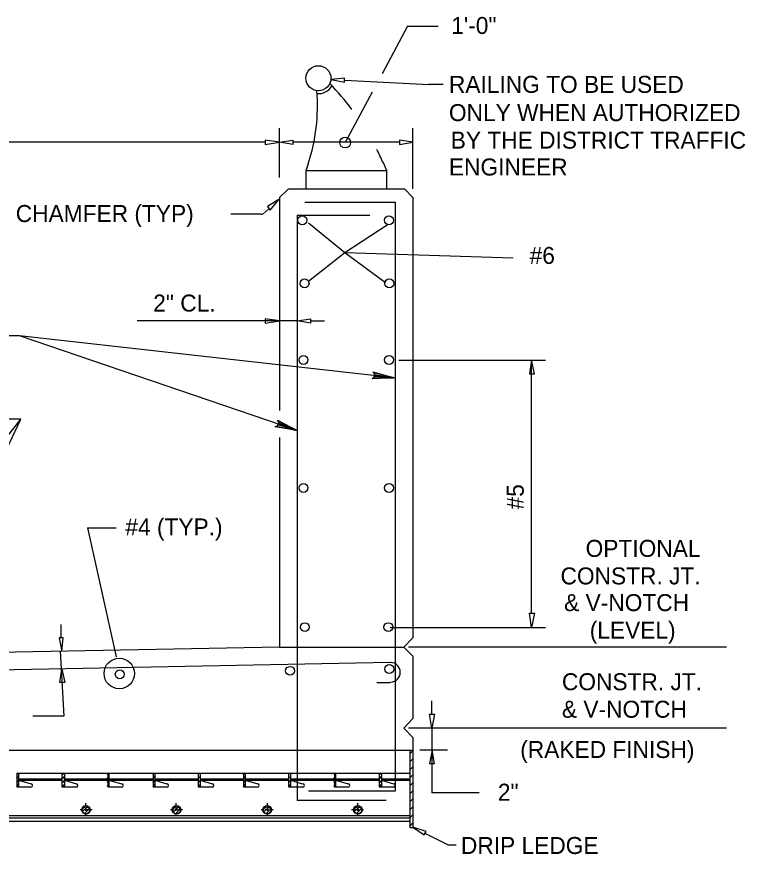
# Model space of a CAD drawing. Extents: x -24512 to -22484, y 4569 to 6351.
# Drawn here: x -23764.3 to -23635.6, y 6048 to 6195.9 of the extents above; entities that cross this region are included whole.
import ezdxf

# ---------------------------------------------------------------- set-up
doc = ezdxf.new("R2010")
doc.units = 0
for name, color, linetype in [('10', 7, 'Continuous'), ('4', 7, 'Continuous'), ('5', 7, 'Continuous'), ('8', 7, 'Continuous'), ('9', 7, 'Continuous')]:
    doc.layers.add(name, color=color, linetype=linetype)

# ---------------------------------------------------------------- blocks, each defined once
blk = doc.blocks.new('JUQ000')
at = {"layer": '4'}
for p, q in [((71.0975, 21.771125), (71.421875, 22.095625)), ((71.237875, 21.6265), (71.566625, 21.95525))]:
    blk.add_line(p, q, dxfattribs=at)
blk = doc.blocks.new('_X')
at = {"layer": '4'}
for p, q in [((63.193375, 24.416625), (63.299125, 24.522375)), ((63.193375, 24.1315), (63.3445, 24.282625)), ((63.193375, 23.846375), (63.3445, 23.9975)), ((63.193375, 23.56125), (63.3445, 23.712375))]:
    blk.add_line(p, q, dxfattribs=at)
blk = doc.blocks.new('JUQ007')
at = {"layer": '4'}
for p, q in [((153.103125, 337.29275), (153.30475, 337.494375)), ((153.103125, 336.7225), (153.30475, 336.924125)), ((153.103125, 336.15225), (153.30475, 336.353875)), ((153.103125, 335.582), (153.30475, 335.783625)), ((153.103125, 335.01175), (153.30475, 335.213375)), ((153.103125, 334.4415), (153.30475, 334.643125)), ((153.103125, 333.87125), (153.30475, 334.072875)), ((153.103125, 333.301), (153.30475, 333.502625)), ((153.103125, 332.73075), (153.30475, 332.932375)), ((153.103125, 332.1605), (153.30475, 332.362125))]:
    blk.add_line(p, q, dxfattribs=at)

msp = doc.modelspace()

# ---------------------------------------------------------------- linework, layer by layer
at = {"layer": '10'}
for p, q in [((-23695.25, 6194.21), (-23699.75, 6185.84)), ((-23695.25, 6194.21), (-23689.87, 6194.21)), ((-23706.41, 6184.7), (-23691.45, 6183.95)), ((-23688.96, 6183.95), (-23691.45, 6183.95)), ((-23701.5, 6182.59), (-23706.28, 6173.69)), ((-23717.89, 6167.5), (-23717.89, 6176.22)), ((-23694.32, 6165.5), (-23694.32, 6176.22)), ((-23720.38, 6173.73), (-23842.45, 6173.73)), ((-23696.69, 6173.73), (-23715.52, 6173.73)), ((-23719.76, 6162.01), (-23720.5, 6161.26)), ((-23721.13, 6161.01), (-23726.49, 6161.01)), ((-23706.33, 6154.19), (-23712.75, 6159.46)), ((-23698.69, 6159.22), (-23706.33, 6154.19)), ((-23706.33, 6154.19), (-23712.75, 6149.17)), ((-23699.18, 6148.93), (-23706.33, 6154.19)), ((-23676.64, 6153.27), (-23706.33, 6154.19)), ((-23714.77, 6142.18), (-23742.99, 6142.18)), ((-23712.4, 6142.18), (-23709.91, 6142.18)), ((-23763.77, 6139.57), (-23778.53, 6139.57)), ((-23697.61, 6132.14), (-23763.77, 6139.57)), ((-23714.77, 6122.84), (-23763.77, 6139.57)), ((-23696.81, 6135.24), (-23670.88, 6135.24)), ((-23673.37, 6090.56), (-23673.37, 6135.24)), ((-23797.56, 6081.71), (-23763.52, 6124.85)), ((-23783.85, 6082.33), (-23763.52, 6124.85)), ((-23763.52, 6124.85), (-23778.92, 6124.85)), ((-23751.76, 6105.63), (-23746.74, 6105.63)), ((-23751.76, 6105.63), (-23746.74, 6082.84)), ((-23756.41, 6086.2), (-23756.41, 6088.57)), ((-23698.31, 6088.07), (-23670.88, 6088.07)), ((-23756.58, 6083.84), (-23755.98, 6072.38)), ((-23638.96, 6084.58), (-23695.07, 6084.58)), ((-23690.95, 6072.73), (-23690.95, 6075.1)), ((-23755.98, 6072.38), (-23761.4, 6072.38)), ((-23638.96, 6070.24), (-23695.07, 6070.24)), ((-23690.95, 6070.24), (-23690.95, 6058.86)), ((-23688.21, 6066.37), (-23693.07, 6066.37)), ((-23682.62, 6058.86), (-23690.95, 6058.86)), ((-23752.05, 6056.4), (-23752.05, 6057.02)), ((-23736.09, 6056.4), (-23736.09, 6057.02)), ((-23720.01, 6056.4), (-23720.01, 6057.02)), ((-23704.05, 6056.4), (-23704.05, 6057.02)), ((-23753.05, 6055.9), (-23752.67, 6055.9)), ((-23752.3, 6055.9), (-23751.8, 6055.9)), ((-23752.05, 6055.65), (-23752.05, 6056.15)), ((-23752.05, 6054.78), (-23752.05, 6055.28)), ((-23751.55, 6055.9), (-23750.93, 6055.9)), ((-23737.09, 6055.9), (-23736.59, 6055.9)), ((-23736.34, 6055.9), (-23735.72, 6055.9)), ((-23736.09, 6055.65), (-23736.09, 6056.15)), ((-23736.09, 6054.78), (-23736.09, 6055.28)), ((-23735.47, 6055.9), (-23734.97, 6055.9)), ((-23721.13, 6055.9), (-23720.63, 6055.9)), ((-23720.38, 6055.9), (-23719.76, 6055.9)), ((-23720.01, 6055.65), (-23720.01, 6056.15)), ((-23720.01, 6054.78), (-23720.01, 6055.28)), ((-23719.51, 6055.9), (-23719.01, 6055.9)), ((-23705.17, 6055.9), (-23704.54, 6055.9)), ((-23704.29, 6055.9), (-23703.8, 6055.9)), ((-23704.05, 6055.65), (-23704.05, 6056.15)), ((-23704.05, 6054.78), (-23704.05, 6055.28)), ((-23703.42, 6055.9), (-23703.05, 6055.9)), ((-23692.08, 6051.66), (-23688.08, 6049.67)), ((-23688.08, 6049.67), (-23686.71, 6049.67))]:
    msp.add_line(p, q, dxfattribs=at)
for points in [[(-23706.41, 6184.33), (-23706.41, 6185.08), (-23708.78, 6184.83)], [(-23720.38, 6174.1), (-23720.38, 6173.36), (-23717.89, 6173.73)], [(-23715.52, 6174.1), (-23715.52, 6173.36), (-23717.89, 6173.73)], [(-23696.69, 6174.1), (-23696.69, 6173.36), (-23694.32, 6173.73)], [(-23720.01, 6162.38), (-23719.51, 6161.76), (-23718.01, 6163.63)], [(-23720.38, 6142.56), (-23720.38, 6141.81), (-23717.89, 6142.18)], [(-23712.4, 6142.56), (-23712.4, 6141.81), (-23714.77, 6142.18)], [(-23673.75, 6132.87), (-23672.87, 6132.87), (-23673.37, 6135.24)], [(-23673.75, 6090.56), (-23672.87, 6090.56), (-23673.37, 6088.07)], [(-23756.04, 6086.2), (-23756.79, 6086.2), (-23756.29, 6083.83)], [(-23755.79, 6078.34), (-23756.66, 6078.34), (-23756.29, 6080.71)], [(-23691.4, 6072.73), (-23690.5, 6072.73), (-23690.95, 6070.24)], [(-23691.39, 6064.01), (-23690.49, 6064.01), (-23690.94, 6066.37)], [(-23692.32, 6051.41), (-23691.95, 6052.04), (-23694.32, 6052.78)]]:
    msp.add_lwpolyline(points, close=True, dxfattribs=at)
for points in [[(-23701.22, 6133.01), (-23701.12, 6132.73), (-23697.61, 6132.14), (-23701.22, 6133.01), (-23701.39, 6133.19), (-23697.61, 6132.14), (-23701.16, 6132.36), (-23701.31, 6132.11), (-23697.61, 6132.14), (-23701.53, 6131.96), (-23701.31, 6132.11)], [(-23718.11, 6124.47), (-23718.07, 6124.17), (-23714.77, 6122.84), (-23718.11, 6124.47), (-23718.24, 6124.68), (-23714.77, 6122.84), (-23718.18, 6123.82), (-23718.39, 6123.61), (-23714.77, 6122.84), (-23718.64, 6123.51), (-23718.39, 6123.61)]]:
    msp.add_lwpolyline(points, dxfattribs=at)
for centre, radius in [((-23706.28, 6173.69), 0.963), ((-23746.16, 6079.92), 2.69)]:
    msp.add_circle(centre, radius, dxfattribs=at)
for centre, start, end in [((-23691.51, 6184.77), 267.3542, 270), ((-23721.13, 6161.81), 270, 313.1659)]:
    msp.add_arc(centre, 0.788, start, end, dxfattribs=at)
at = {"layer": '5'}
for p, q in [((-23756.29, 6062.26), (-23763.9, 6062.26)), ((-23756.29, 6061.26), (-23763.9, 6061.26)), ((-23756.29, 6061.01), (-23763.9, 6061.01)), ((-23761.65, 6060.39), (-23763.9, 6061.01)), ((-23748.18, 6062.26), (-23755.79, 6062.26)), ((-23748.18, 6061.26), (-23755.79, 6061.26)), ((-23748.18, 6061.01), (-23755.79, 6061.01)), ((-23753.67, 6060.39), (-23755.79, 6061.01)), ((-23740.2, 6062.26), (-23747.94, 6062.26)), ((-23740.2, 6061.26), (-23747.94, 6061.26)), ((-23740.2, 6061.01), (-23747.94, 6061.01)), ((-23745.69, 6060.39), (-23747.94, 6061.01)), ((-23732.22, 6062.26), (-23739.83, 6062.26)), ((-23732.22, 6061.26), (-23739.83, 6061.26)), ((-23732.22, 6061.01), (-23739.83, 6061.01)), ((-23737.71, 6060.39), (-23739.83, 6061.01)), ((-23724.24, 6062.26), (-23731.85, 6062.26)), ((-23724.24, 6061.26), (-23731.85, 6061.26)), ((-23724.24, 6061.01), (-23731.85, 6061.01)), ((-23729.73, 6060.39), (-23731.85, 6061.01)), ((-23716.26, 6062.26), (-23723.87, 6062.26)), ((-23716.26, 6061.26), (-23723.87, 6061.26)), ((-23716.26, 6061.01), (-23723.87, 6061.01)), ((-23721.63, 6060.39), (-23723.87, 6061.01)), ((-23708.16, 6062.26), (-23715.89, 6062.26)), ((-23708.16, 6061.26), (-23715.89, 6061.26)), ((-23708.16, 6061.01), (-23715.89, 6061.01)), ((-23713.77, 6060.39), (-23715.89, 6061.01)), ((-23700.3, 6062.26), (-23707.91, 6062.26)), ((-23700.3, 6061.26), (-23707.91, 6061.26)), ((-23700.3, 6061.01), (-23707.91, 6061.01)), ((-23705.67, 6060.39), (-23707.91, 6061.01)), ((-23694.82, 6062.26), (-23699.81, 6062.26)), ((-23694.82, 6061.26), (-23699.81, 6061.26)), ((-23694.82, 6061.01), (-23699.81, 6061.01)), ((-23697.69, 6060.39), (-23699.81, 6061.01)), ((-23763.9, 6059.89), (-23761.78, 6059.89)), ((-23755.79, 6059.89), (-23753.67, 6059.89)), ((-23747.94, 6059.89), (-23745.82, 6059.89)), ((-23739.83, 6059.89), (-23737.71, 6059.89)), ((-23731.85, 6059.89), (-23729.73, 6059.89)), ((-23723.87, 6059.89), (-23721.75, 6059.89)), ((-23715.89, 6059.89), (-23713.77, 6059.89)), ((-23707.91, 6059.89), (-23705.79, 6059.89)), ((-23699.81, 6059.89), (-23697.69, 6059.89)), ((-23694.82, 6054.78), (-23884.97, 6054.78)), ((-23694.82, 6054.4), (-23884.97, 6054.4)), ((-23694.82, 6053.78), (-23884.97, 6053.78))]:
    msp.add_line(p, q, dxfattribs=at)
for points in [[(-23694.32, 6052.66), (-23694.82, 6052.66), (-23694.82, 6066.37), (-23694.32, 6066.37)], [(-23764.27, 6062.26), (-23764.27, 6059.89), (-23763.9, 6059.89), (-23763.9, 6062.26)], [(-23756.29, 6062.26), (-23756.29, 6059.89), (-23755.79, 6059.89), (-23755.79, 6062.26)], [(-23748.18, 6062.26), (-23748.18, 6059.89), (-23747.94, 6059.89), (-23747.94, 6062.26)], [(-23740.2, 6062.26), (-23740.2, 6059.89), (-23739.83, 6059.89), (-23739.83, 6062.26)], [(-23732.22, 6062.26), (-23732.22, 6059.89), (-23731.85, 6059.89), (-23731.85, 6062.26)], [(-23724.24, 6062.26), (-23724.24, 6059.89), (-23723.87, 6059.89), (-23723.87, 6062.26)], [(-23716.26, 6062.26), (-23716.26, 6059.89), (-23715.89, 6059.89), (-23715.89, 6062.26)], [(-23708.16, 6062.26), (-23708.16, 6059.89), (-23707.91, 6059.89), (-23707.91, 6062.26)], [(-23700.3, 6062.26), (-23700.3, 6059.89), (-23699.81, 6059.89), (-23699.81, 6062.26)]]:
    msp.add_lwpolyline(points, close=True, dxfattribs=at)
for centre, radius in [((-23752.05, 6055.86), 0.75), ((-23736.05, 6055.86), 0.75), ((-23720.05, 6055.86), 0.75), ((-23704.04, 6055.86), 0.75), ((-23752.05, 6055.74), 0.625), ((-23736.05, 6055.74), 0.625), ((-23720.05, 6055.74), 0.625), ((-23704.04, 6055.74), 0.625)]:
    msp.add_circle(centre, radius, dxfattribs=at)
for centre in [(-23761.76, 6060.15), (-23753.76, 6060.15), (-23745.76, 6060.15), (-23737.76, 6060.15), (-23729.76, 6060.15), (-23721.76, 6060.15), (-23713.76, 6060.15), (-23705.76, 6060.15), (-23697.75, 6060.15)]:
    msp.add_arc(centre, 0.305, 271.249, 76.5605, dxfattribs=at)
at = {"layer": '8'}
for p, q in [((-23713.41, 6163.16), (-23697.44, 6163.16)), ((-23697.44, 6163.16), (-23697.44, 6059.14)), ((-23714.77, 6160.88), (-23701.9, 6160.88)), ((-23714.77, 6160.88), (-23714.77, 6057.52)), ((-23698.31, 6081.84), (-23789.58, 6080.09)), ((-23700.68, 6078.34), (-23698.31, 6078.34)), ((-23697.44, 6059.14), (-23712.77, 6059.14)), ((-23699.06, 6057.52), (-23714.77, 6057.52))]:
    msp.add_line(p, q, dxfattribs=at)
for centre in [(-23713.83, 6159.96), (-23698.56, 6159.96), (-23713.45, 6148.81), (-23698.48, 6148.81), (-23713.64, 6135.3), (-23698.54, 6135.3), (-23713.64, 6112.7), (-23698.54, 6112.7), (-23713.4, 6088.11), (-23698.64, 6088.11), (-23746.07, 6079.78), (-23716, 6080.4), (-23698.5, 6080.71)]:
    msp.add_circle(centre, 0.788, dxfattribs=at)
msp.add_arc((-23698.27, 6080.14), 1.73, 270, 90, dxfattribs=at)
at = {"layer": '9'}
for p, q in [((-23713.15, 6168.74), (-23712.77, 6169.99)), ((-23698.93, 6168.74), (-23699.56, 6170.24)), ((-23713.15, 6165.5), (-23713.15, 6168.74)), ((-23713.15, 6168.74), (-23698.93, 6168.74)), ((-23698.93, 6165.5), (-23698.93, 6168.74)), ((-23717.89, 6164), (-23716.26, 6165.5)), ((-23716.26, 6165.5), (-23695.82, 6165.5)), ((-23695.82, 6165.5), (-23694.32, 6164)), ((-23717.89, 6164), (-23717.89, 6126.39)), ((-23694.32, 6164), (-23694.32, 6086.2)), ((-23717.89, 6121.57), (-23717.89, 6084.58)), ((-23694.32, 6086.2), (-23695.94, 6084.58)), ((-23717.89, 6084.58), (-23842.45, 6082.21)), ((-23717.89, 6084.58), (-23695.94, 6084.58)), ((-23694.32, 6082.96), (-23695.94, 6084.58)), ((-23694.32, 6082.96), (-23694.32, 6071.99)), ((-23694.32, 6071.99), (-23695.94, 6070.24)), ((-23694.32, 6068.62), (-23695.94, 6070.24)), ((-23694.32, 6068.62), (-23694.32, 6066.37)), ((-23842.18, 6066.37), (-23694.32, 6066.37))]:
    msp.add_line(p, q, dxfattribs=at)
msp.add_circle((-23711, 6185.04), 2.21, dxfattribs=at)
for centre, radius, start, end in [((-23711, 6185.04), 2.72, 264.5039, 330.691), ((-23743.31, 6150.83), 47.8, 36.8913, 44.1234), ((-23743.26, 6180.02), 32.09, 341.6818, 5.0649), ((-23743.31, 6150.83), 47.8, 23.8916, 26.9415)]:
    msp.add_arc(centre, radius, start, end, dxfattribs=at)

# ---------------------------------------------------------------- block references
at = {"layer": '4'}
for name, p, xscale, yscale in [('JUQ007', (-24074.62, 5229.1), 2.4803976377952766, 2.4803976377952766), ('_X', (-23921, 6001.54), 2.4803976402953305, 2.4803976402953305), ('_X', (-23912.9, 6001.54), 2.4803976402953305, 2.4803976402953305), ('_X', (-23905.04, 6001.54), 2.4803976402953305, 2.4803976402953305), ('_X', (-23896.94, 6001.54), 2.4803976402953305, 2.4803976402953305), ('_X', (-23888.96, 6001.54), 2.4803976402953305, 2.4803976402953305), ('_X', (-23880.98, 6001.54), 2.4803976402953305, 2.4803976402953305), ('_X', (-23873, 6001.54), 2.4803976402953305, 2.4803976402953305), ('_X', (-23865.02, 6001.54), 2.4803976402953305, 2.4803976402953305), ('_X', (-23856.91, 6001.54), 2.4803976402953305, 2.4803976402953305), ('JUQ000', (-23928.98, 6001.54), 2.4803976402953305, 2.4803976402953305), ('JUQ000', (-23912.9, 6001.54), 2.4803976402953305, 2.4803976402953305), ('JUQ000', (-23896.94, 6001.54), 2.4803976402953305, 2.4803976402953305), ('JUQ000', (-23880.98, 6001.54), 2.4803976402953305, 2.4803976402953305)]:
    msp.add_blockref(name, p, dxfattribs=dict(at, xscale=xscale, yscale=yscale))

# ---------------------------------------------------------------- texts
at = {"layer": '10'}
for s, p in [('1\'-0"', (-23687.55, 6192.86)), ('RAILING TO BE USED ', (-23687.96, 6182.46)), ('ONLY WHEN AUTHORIZED ', (-23687.96, 6177.47)), ('BY THE DISTRICT TRAFFIC', (-23687.64, 6172.61)), ('ENGINEER', (-23687.96, 6167.87)), ('CHAMFER (TYP)', (-23764.44, 6159.65)), ('#6', (-23673.71, 6152.25)), ('2" CL.', (-23740.17, 6143.84)), ('#4 (TYP.)', (-23745.09, 6104.3)), ('OPTIONAL', (-23663.83, 6100.52)), ('CONSTR. JT.', (-23668.26, 6095.65)), ('& V-NOTCH', (-23667.62, 6090.94)), ('(LEVEL)', (-23663.1, 6086.08)), ('CONSTR. JT.', (-23668.01, 6076.97)), ('& V-NOTCH', (-23668.01, 6072.11)), ('(RAKED FINISH)', (-23675.37, 6065)), ('2"', (-23679.32, 6057.46)), ('DRIP LEDGE', (-23685.84, 6048.05))]:
    msp.add_text(s, height=3, dxfattribs=at).set_placement(p)
msp.add_text('#5 ', height=3, rotation=90, dxfattribs=at).set_placement((-23674.75, 6108.89))

doc.saveas('drawing.dxf')
